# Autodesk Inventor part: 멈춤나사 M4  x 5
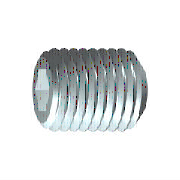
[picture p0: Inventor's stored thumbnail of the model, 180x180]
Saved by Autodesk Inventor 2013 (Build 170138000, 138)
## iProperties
IsCustomPart: 1
Created: 2012-02
Part Number: 멈춤나사 M4  x 5
Material: 강철, 연강
Description: 6각 소켓 머리 없는 멈춤 나사
Document SubType Name: Modeling
Standard: KS B 1028
Designer: mduedu
Standards Organization: KS
Language: ko-KR
Size Designation: 납작점M4x5
Categories: <MemberInstance><Categories><Category DisplayName="조임쇠" InternalName="e4da775c-781d-43d5-af7c-5136215cf5a6" Mnemonic="FSTN"><Category DisplayName="볼트" InternalN
Density: 7.86 g/cm^3
Mass: 0.401763 g
Surface Area: 0.994256 cm^2
Volume: 0.0511149 cm^3
Author: mduedu
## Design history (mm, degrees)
sketch "스케치1"
  geometry: L1 (0, 0)-(1.833, 0); L2 (5, 1.155)-(5, 2); L3 (5, 2)-(0, 2); L4 (5, 1.155)-(2.5, 1.155); L5 (2.5, 1.155)-(1.833, 0); L6 (0, -0.4)-(0, 2.4) reference; L7 (0, 2)-(0, 0)
  constraints: 13 end point, 3 parallel, 1 collinear, 1 perpendicular, 1 point on line
  dimensions: "d0" = 2.5 distance of L2.start L4.end (= INTI); "d1" = 60 deg angle of L5 L1; "d2" = 4 diameter of L3 L1 (= NND); "d3" = 2.3094 diameter of L4 L1 (= 1.1547 x SW); "d5" = 5 distance from line of L2 L3.end (= NLG)
revolve "본체" sketch "스케치1" stored, may be unused: angle "d6" = 90 deg
sketch "스케치2"
  geometry: L1 (-0.577, 1)-(0.577, 1); L2 (0.577, 1)-(1.155, 0); L3 (1.155, 0)-(0.577, -1); L4 (0.577, -1)-(-0.577, -1); L5 (-0.577, -1)-(-1.155, 0); L6 (-1.155, 0)-(-0.577, 1); A1 r 1.155 centre (0, 0) between (-0.577, 1) and (0.577, 1) reference; 2 further points
  constraints: 12 end point, 2 point on circle, 1 coincident, 1 horizontal, 11 other
extrude "슬롯" join sketch "스케치2" taper "d9" = 0 deg; stored distance "d21" = 10
workaxis "Work Axis1"
workplane "Work Plane1"
body "Solid1"
chamfer "모따기1" distance "d7" = 0.42941 (= -0.5 x GD1 + 0.5 x NND); stored, may be unused: angle "d8" = 45 deg (= FAWI), second distance "d29" = 0.42941 (= -0.5 x GD1 + 0.5 x NND)
feature "스레드" dims "d11" = 5 (= NLG), "d12" = 0
chamfer "모따기2" distance "d13" = 0.42941 (= -0.5 x GD1 + 0.5 x NND); stored, may be unused: angle "d14" = 45 deg (= FAWI), second distance "d30" = 0.42941 (= -0.5 x GD1 + 0.5 x NND)
other parameters: "NND" = 4 [user parameter; used in 5 equation terms], "NLG" = 5 [user parameter; used in 2 equation terms], "INTI" = 2.5 [user parameter; used in 1 equation term], "FAWI" = 45 deg [user parameter; used in 2 equation terms], "SW" = 2 [user parameter; used in 2 equation terms], "GD1" = 3.14117 (= THREADDIA - 1.2269 x PTC) [user parameter; used in 4 equation terms], "d4" = 0, "FAWI1" = 45 deg [user parameter], "d15" = 0, "d31" = 0, "GUL" = 0.42941 (= 0.61345 x PTC) [user parameter], "SPD" = 2.5 [user parameter], "TPU" = 14.28571 (computed from PTC) [user parameter], "TOA" = 30 deg [user parameter], "THREADDIA" = 4 [user parameter; used in 1 equation term], "PTC" = 0.7 [user parameter; used in 4 equation terms], "GAL" = 0.42941 (= 0.61345 x PTC) [user parameter], "E0" = 2.31 (= 1.155 x SW) [user parameter]
